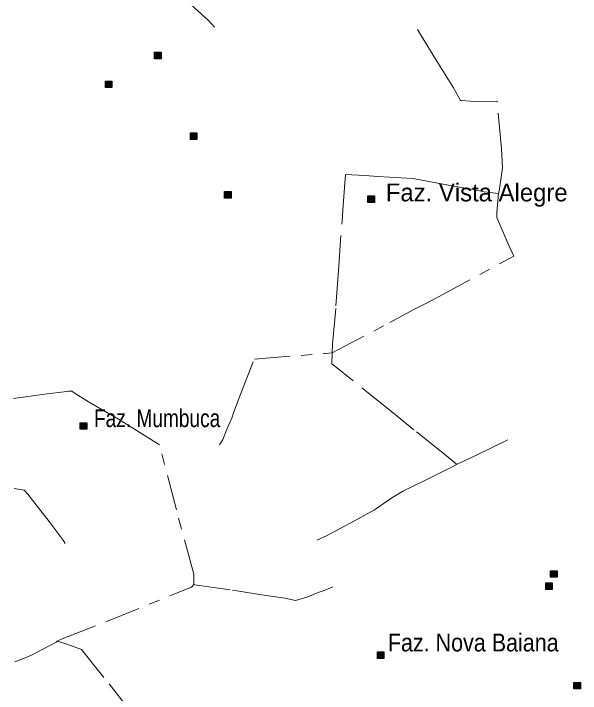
# Model space of a CAD drawing. Extents: x 393.5 to 446.9, y 8064.8 to 8120.4.
# Drawn here: x 393.73 to 398.81, y 8080.11 to 8086.21 of the extents above; entities that cross this region are included whole.
import ezdxf

# ---------------------------------------------------------------- set-up
doc = ezdxf.new("R2010")
doc.units = 0
doc.header["$LTSCALE"] = 0.064
doc.linetypes.add('DOT_DASHED', pattern=[7.7, 5, -1.2, 0.3, -1.2])
doc.layers.add('2', color=7, linetype='Continuous', lineweight=25)
doc.layers.add('22', color=7, linetype='DOT_DASHED', lineweight=13)
doc.layers.add('61', color=7, linetype='Continuous')

msp = doc.modelspace()

# ---------------------------------------------------------------- hatches: boundary and pattern name
at = {"layer": '2'}
for points in [[(394.9964, 8085.8594), (395.0544, 8085.8594), (395.0544, 8085.8014), (394.9964, 8085.8014)], [(394.5559, 8085.6004), (394.6139, 8085.6004), (394.6139, 8085.5424), (394.5559, 8085.5424)], [(395.3172, 8085.1362), (395.3752, 8085.1362), (395.3752, 8085.0782), (395.3172, 8085.0782)], [(395.6244, 8084.6099), (395.6824, 8084.6099), (395.6824, 8084.5519), (395.6244, 8084.5519)], [(396.9081, 8084.571), (396.9661, 8084.571), (396.9661, 8084.513), (396.9081, 8084.513)], [(394.3302, 8082.5399), (394.3882, 8082.5399), (394.3882, 8082.4819), (394.3302, 8082.4819)], [(398.5458, 8081.2127), (398.6038, 8081.2127), (398.6038, 8081.1547), (398.5458, 8081.1547)], [(398.5015, 8081.1044), (398.5595, 8081.1044), (398.5595, 8081.0464), (398.5015, 8081.0464)], [(396.9937, 8080.4859), (397.0517, 8080.4859), (397.0517, 8080.4279), (396.9937, 8080.4279)], [(398.7543, 8080.2124), (398.8123, 8080.2124), (398.8123, 8080.1544), (398.7543, 8080.1544)]]:
    msp.add_hatch(color=256, dxfattribs=at).paths.add_polyline_path(points)

# ---------------------------------------------------------------- linework, layer by layer
for points in [[(394.9964, 8085.8594), (395.0544, 8085.8594), (395.0544, 8085.8014), (394.9964, 8085.8014)], [(394.5559, 8085.6004), (394.6139, 8085.6004), (394.6139, 8085.5424), (394.5559, 8085.5424)], [(395.3172, 8085.1362), (395.3752, 8085.1362), (395.3752, 8085.0782), (395.3172, 8085.0782)], [(395.6244, 8084.6099), (395.6824, 8084.6099), (395.6824, 8084.5519), (395.6244, 8084.5519)], [(396.9081, 8084.571), (396.9661, 8084.571), (396.9661, 8084.513), (396.9081, 8084.513)], [(394.3302, 8082.5399), (394.3882, 8082.5399), (394.3882, 8082.4819), (394.3302, 8082.4819)], [(398.5458, 8081.2127), (398.6038, 8081.2127), (398.6038, 8081.1547), (398.5458, 8081.1547)], [(398.5015, 8081.1044), (398.5595, 8081.1044), (398.5595, 8081.0464), (398.5015, 8081.0464)], [(396.9937, 8080.4859), (397.0517, 8080.4859), (397.0517, 8080.4279), (396.9937, 8080.4279)], [(398.7543, 8080.2124), (398.8123, 8080.2124), (398.8123, 8080.1544), (398.7543, 8080.1544)]]:
    msp.add_lwpolyline(points, close=True, dxfattribs=at)
at = {"layer": '22'}
for p, q in [((397.7031, 8082.1657), (397.6983, 8082.1699)), ((394.1229, 8080.5832), (394.1286, 8080.5858))]:
    msp.add_line(p, q, dxfattribs=at)
for points in [[(395.2029, 8086.9355), (395.1663, 8086.9172), (395.1102, 8086.8835), (395.1102, 8086.8499), (395.1437, 8086.6096), (395.1568, 8086.4844), (395.1624, 8086.4377), (395.2017, 8086.3965), (395.357, 8086.2545), (395.4804, 8086.1442), (395.5347, 8086.0844)], [(397.7482, 8085.4269), (397.7364, 8085.4273), (397.6758, 8085.5407), (397.5261, 8085.7802), (397.3807, 8086.0166), (397.3512, 8086.0642)], [(398.0796, 8084.593), (398.0834, 8084.6156), (398.1145, 8084.8246), (398.1067, 8084.9946), (398.0658, 8085.4213), (397.8638, 8085.419), (397.7482, 8085.4269)], [(396.5888, 8083.1648), (396.5919, 8083.2442), (396.6214, 8083.5861), (396.6436, 8083.8992), (396.6761, 8084.3472), (396.6862, 8084.4886), (396.7079, 8084.7631), (396.8804, 8084.754), (396.9961, 8084.7472), (397.3116, 8084.7268), (397.5193, 8084.6882), (397.6623, 8084.661), (397.8358, 8084.6337), (397.9493, 8084.6088), (398.0769, 8084.5933), (398.0796, 8084.593)], [(397.5397, 8083.6687), (398.2148, 8084.0315), (398.1626, 8084.1494), (398.0628, 8084.3785), (398.0628, 8084.4238), (398.0796, 8084.593)], [(396.5888, 8083.1648), (397.1044, 8083.4367), (397.32, 8083.5547), (397.4085, 8083.6), (397.5397, 8083.6687)], [(395.7037, 8082.6275), (395.7627, 8082.7863), (395.8908, 8083.1083), (396.5251, 8083.1605), (396.5888, 8083.1648)], [(397.6983, 8082.1699), (397.5951, 8082.2584), (397.3201, 8082.4769), (397.1039, 8082.6523), (396.6945, 8082.9808), (396.585, 8083.0672), (396.5888, 8083.1648)], [(394.211, 8082.8195), (394.0085, 8082.7946), (393.733, 8082.7555)], [(395.3474, 8081.0896), (395.348, 8081.1279), (395.348, 8081.1815), (395.1915, 8081.7578), (395.0402, 8082.3415), (394.9135, 8082.4219), (394.6722, 8082.5704), (394.4029, 8082.7262), (394.2835, 8082.8017), (394.2543, 8082.8236), (394.2251, 8082.8236), (394.211, 8082.8195)], [(395.5787, 8082.3403), (395.6094, 8082.3883), (395.6459, 8082.4881), (395.6874, 8082.5807), (395.7037, 8082.6275)], [(398.1605, 8082.3858), (397.8857, 8082.2522), (397.7591, 8082.1923), (397.7031, 8082.1657)], [(396.4504, 8081.4858), (396.5438, 8081.5278), (396.7866, 8081.6593), (396.9659, 8081.7591), (397.1225, 8081.8679), (397.2257, 8081.9292), (397.4073, 8082.0154), (397.6751, 8082.1492), (397.7031, 8082.1657)], [(393.7372, 8081.9507), (393.8291, 8081.936), (393.8602, 8081.8985), (394.0511, 8081.6555), (394.1785, 8081.4858), (394.1964, 8081.4565)], [(394.1286, 8080.5858), (394.1696, 8080.6045), (394.559, 8080.7564), (395.1977, 8081.014), (395.3261, 8081.0671), (395.3474, 8081.0896)], [(395.3474, 8081.0896), (395.3495, 8081.0893), (395.3577, 8081.0881)], [(395.3577, 8081.0881), (395.6951, 8081.0385), (395.9949, 8080.9926), (396.1639, 8080.9669), (396.2594, 8080.9453), (396.369, 8080.9794), (396.4113, 8080.9984)], [(396.4113, 8080.9984), (396.4459, 8081.0131), (396.5309, 8081.0433), (396.5929, 8081.0686)], [(393.7454, 8080.3975), (393.8885, 8080.4537), (394.1132, 8080.573), (394.1229, 8080.5832)], [(394.1229, 8080.5832), (394.1752, 8080.5662), (394.2607, 8080.537), (394.3424, 8080.5079), (394.5885, 8080.2008), (394.8248, 8079.8977), (395.024, 8079.6256), (395.2166, 8079.3807), (395.324, 8079.2413), (395.3708, 8079.1894), (395.428, 8079.1807), (395.5702, 8079.1738), (395.5724, 8079.1736)]]:
    msp.add_lwpolyline(points, dxfattribs=at)

# ---------------------------------------------------------------- texts
at = {"layer": '61'}
msp.add_text('Faz. Vista Alegre', height=0.16, dxfattribs=at).set_placement((397.0687, 8084.5228))
for s, width, p in [('Faz. Mumbuca', 0.8, (394.4532, 8082.5003)), ('Faz. Nova Baiana', 0.9, (397.0868, 8080.4901))]:
    msp.add_text(s, height=0.16, dxfattribs=dict(at, width=width)).set_placement(p)

doc.saveas('drawing.dxf')
